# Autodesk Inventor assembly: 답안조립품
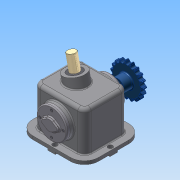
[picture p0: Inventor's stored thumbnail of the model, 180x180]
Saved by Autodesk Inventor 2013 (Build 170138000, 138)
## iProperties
Created: 2014-11
Part Number: 답안조립품
Document SubType Name: Assembly
Designer: Administrator
Author: Administrator
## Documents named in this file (13)
- C:\Users\Administrator\Desktop\441123V1006\답안조립품.iam
- C:\Users\Administrator\Desktop\441123V1006\본체.ipt
- C:\Users\Administrator\Desktop\441123V1006\5-체인 스프로킷.ipt
- C:\Users\Administrator\Desktop\441123V1006\M4x0.5.ipt
- C:\Users\Administrator\Desktop\441123V1006\뒤커버.ipt
- C:\Users\Administrator\Desktop\441123V1006\멈춤나사 M5x0.5.ipt
- C:\Users\Administrator\Desktop\441123V1006\베어링 6205.ipt
- C:\Users\Administrator\Desktop\441123V1006\부시.ipt
- C:\Users\Administrator\Desktop\441123V1006\슬라이드.ipt
- C:\Users\Administrator\Desktop\441123V1006\앞커버.ipt
- C:\Users\Administrator\Desktop\441123V1006\오일실.ipt
- C:\Users\Administrator\Desktop\441123V1006\키 8x8.ipt
- C:\Users\Administrator\Desktop\441123V1006\편심축.ipt
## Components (9 placed, 2 different names)
1. 5-체인 스프로킷:1 — Mate:13, Mate:14, Flush:1, Mate:23
2. M4x0.5:1 — Mate:7, Mate:8
3. M4x0.5:3
4. M4x0.5:4
5. M4x0.5:5
6. M4x0.5:2 — Mate:9, Mate:10
7. M4x0.5:6
8. M4x0.5:7
9. M4x0.5:8
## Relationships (8: Mate 7, Flush 1)
- Mate:7: M4x0.5:1
- Mate:8: M4x0.5:1
- Mate:9: M4x0.5:2
- Mate:10: M4x0.5:2
- Mate:13: 5-체인 스프로킷:1
- Mate:14: 5-체인 스프로킷:1
- Flush:1: 5-체인 스프로킷:1
- Mate:23: 5-체인 스프로킷:1
